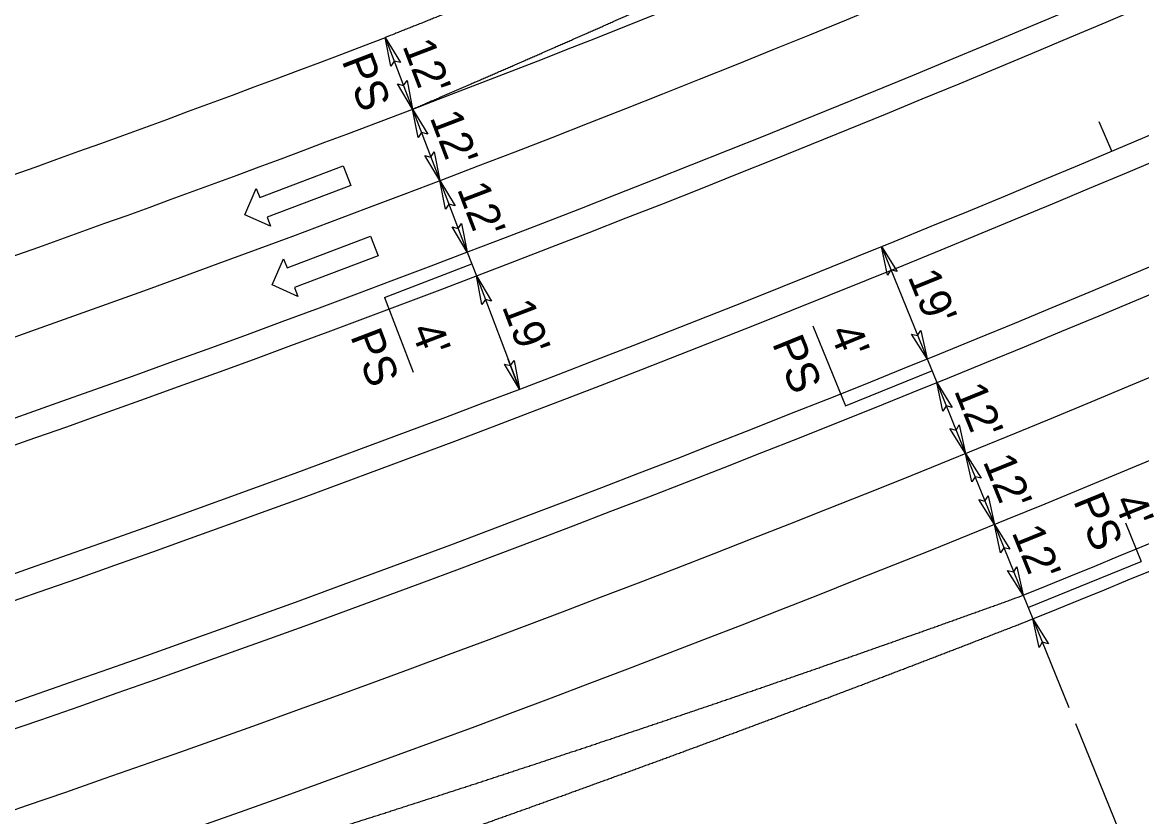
# Model space of a CAD drawing. Extents: x 2389694 to 2405615, y 546931 to 573532.
# Drawn here: x 2391294.1 to 2391469.5, y 552698.7 to 552823.2 of the extents above; entities that cross this region are included whole.
import ezdxf

# ---------------------------------------------------------------- set-up
doc = ezdxf.new("R2010")
doc.units = 0
for name, color, linetype in [('Prop Cable Guiderail Double Face', 7, 'Continuous'), ('Prop Dimension', 7, 'Continuous'), ('Prop Dimension Text', 7, 'Continuous'), ('Prop EOT', 7, 'Continuous'), ('Prop Horizontal Alignment', 7, 'Continuous'), ('Prop Horizontal Alignment Tick Small', 7, 'Continuous'), ('Prop Lane Arrow Through CELL', 7, 'Continuous'), ('Prop Lane Lines', 7, 'Continuous')]:
    doc.layers.add(name, color=color, linetype=linetype)

msp = doc.modelspace()

# ---------------------------------------------------------------- linework, layer by layer
at = {"layer": 'Prop Cable Guiderail Double Face'}
msp.add_arc((2390350.01, 555442.22), 2869, 286.11768, 302.22693, dxfattribs=at)
at = {"layer": 'Prop Dimension'}
for p, q in [((2391350.94, 552820.82), (2391355.22, 552809.61)), ((2391355.22, 552809.61), (2391359.5, 552798.4)), ((2391359.5, 552798.4), (2391363.78, 552787.19)), ((2391428.68, 552788.04), (2391435.84, 552770.44)), ((2391363.78, 552787.19), (2391365.21, 552783.45)), ((2391350.8, 552780.09), (2391364.5, 552785.32)), ((2391365.21, 552783.45), (2391371.99, 552765.7)), ((2391350.8, 552780.09), (2391355.28, 552768.37)), ((2391417.95, 552775.62), (2391423.04, 552763.08)), ((2391435.84, 552770.44), (2391437.34, 552766.73)), ((2391423.04, 552763.08), (2391436.59, 552768.59)), ((2391437.34, 552766.73), (2391441.86, 552755.62)), ((2391441.86, 552755.62), (2391446.38, 552744.5)), ((2391446.38, 552744.5), (2391450.9, 552733.38)), ((2391466.94, 552744.76), (2391469.4, 552738.69)), ((2391451.79, 552731.53), (2391469.4, 552738.69)), ((2391450.9, 552733.38), (2391452.41, 552729.68)), ((2391452.41, 552729.68), (2391458.05, 552715.78)), ((2391459.07, 552713.28), (2391468.06, 552691.16))]:
    msp.add_line(p, q, dxfattribs=at)
for points in [[(2391351.82, 552816.34), (2391350.94, 552820.82), (2391353.3, 552816.88), (2391352.35, 552817.13)], [(2391354.34, 552814.09), (2391355.22, 552809.61), (2391352.86, 552813.55), (2391353.81, 552813.3)], [(2391356.1, 552805.13), (2391355.22, 552809.61), (2391357.58, 552805.67), (2391356.63, 552805.92)], [(2391358.62, 552802.88), (2391359.5, 552798.4), (2391357.14, 552802.34), (2391358.09, 552802.09)], [(2391360.38, 552793.92), (2391359.5, 552798.4), (2391361.87, 552794.46), (2391360.91, 552794.71)], [(2391362.9, 552791.67), (2391363.78, 552787.19), (2391361.42, 552791.13), (2391362.38, 552790.88)], [(2391429.66, 552783.58), (2391428.68, 552788.04), (2391431.13, 552784.15), (2391430.17, 552784.38)], [(2391366.09, 552778.97), (2391365.21, 552783.45), (2391367.57, 552779.51), (2391366.62, 552779.76)], [(2391434.86, 552774.9), (2391435.84, 552770.44), (2391433.39, 552774.33), (2391434.35, 552774.1)], [(2391371.11, 552770.18), (2391371.99, 552765.7), (2391369.63, 552769.64), (2391370.58, 552769.39)], [(2391438.32, 552762.27), (2391437.34, 552766.73), (2391439.79, 552762.84), (2391438.83, 552763.07)], [(2391440.89, 552760.08), (2391441.86, 552755.62), (2391439.42, 552759.51), (2391440.38, 552759.28)], [(2391442.84, 552751.16), (2391441.86, 552755.62), (2391444.31, 552751.72), (2391443.35, 552751.96)], [(2391445.4, 552748.96), (2391446.38, 552744.5), (2391443.94, 552748.39), (2391444.89, 552748.16)], [(2391447.36, 552740.04), (2391446.38, 552744.5), (2391448.83, 552740.61), (2391447.87, 552740.84)], [(2391449.92, 552737.84), (2391450.9, 552733.38), (2391448.45, 552737.27), (2391449.41, 552737.04)], [(2391453.38, 552725.21), (2391452.41, 552729.68), (2391454.85, 552725.78), (2391453.89, 552726.02)]]:
    msp.add_lwpolyline(points, close=True, dxfattribs=at)
at = {"layer": 'Prop EOT'}
for radius, start, end in [(2842, 286.11768, 302.22693), (2846, 286.11763, 302.22693), (2884, 286.11768, 302.22693), (2888, 286.11768, 302.22693), (2924, 292.11719, 302.22692), (2928, 292.11719, 302.22692), (2806, 286.11768, 290.89848), (2818, 286.11768, 290.89849)]:
    msp.add_arc((2390350.01, 555442.22), radius, start, end, dxfattribs=at)
for points in [[(2391405.32, 552843.1), (2391404.59, 552842.79), (2391403.85, 552842.48), (2391403.12, 552842.17), (2391402.39, 552841.86), (2391401.66, 552841.56), (2391400.93, 552841.25), (2391400.19, 552840.94), (2391399.46, 552840.63), (2391398.73, 552840.32), (2391398, 552840.02), (2391397.26, 552839.71), (2391396.53, 552839.41), (2391395.8, 552839.1), (2391395.07, 552838.79), (2391394.34, 552838.49), (2391393.6, 552838.18), (2391392.87, 552837.88), (2391392.14, 552837.57), (2391391.4, 552837.27), (2391390.67, 552836.96), (2391389.93, 552836.66), (2391389.2, 552836.35), (2391388.47, 552836.05), (2391387.73, 552835.75), (2391387, 552835.44), (2391386.27, 552835.14), (2391385.54, 552834.84), (2391384.8, 552834.53), (2391384.07, 552834.23), (2391383.34, 552833.93), (2391382.59, 552833.62), (2391381.86, 552833.32), (2391381.13, 552833.02), (2391380.39, 552832.72), (2391379.66, 552832.42), (2391378.92, 552832.12), (2391378.19, 552831.82), (2391377.46, 552831.51), (2391376.72, 552831.21), (2391375.99, 552830.91), (2391375.25, 552830.61), (2391374.52, 552830.31), (2391373.78, 552830.01), (2391373.04, 552829.71), (2391372.31, 552829.41), (2391371.57, 552829.11), (2391370.84, 552828.81), (2391370.1, 552828.52), (2391369.37, 552828.22), (2391368.63, 552827.92), (2391367.9, 552827.62), (2391367.16, 552827.32), (2391366.42, 552827.03), (2391365.69, 552826.73), (2391364.95, 552826.43), (2391364.21, 552826.13), (2391363.47, 552825.83), (2391362.74, 552825.54), (2391362, 552825.24), (2391361.27, 552824.95), (2391360.53, 552824.65), (2391359.79, 552824.35), (2391359.06, 552824.06), (2391358.32, 552823.76), (2391357.58, 552823.47), (2391356.85, 552823.17), (2391356.11, 552822.88), (2391355.36, 552822.58), (2391354.63, 552822.29), (2391353.89, 552821.99), (2391353.15, 552821.7), (2391352.42, 552821.41), (2391350.94, 552820.82)], [(2391355.22, 552809.61), (2391355.96, 552809.92), (2391356.69, 552810.24), (2391357.42, 552810.55), (2391358.15, 552810.87), (2391358.89, 552811.18), (2391359.62, 552811.5), (2391360.36, 552811.82), (2391361.09, 552812.13), (2391361.82, 552812.45), (2391362.56, 552812.77), (2391363.29, 552813.08), (2391364.02, 552813.4), (2391364.75, 552813.72), (2391365.48, 552814.03), (2391366.21, 552814.35), (2391366.94, 552814.67), (2391367.67, 552814.99), (2391368.41, 552815.31), (2391369.15, 552815.63), (2391369.88, 552815.95), (2391370.61, 552816.26), (2391371.34, 552816.58), (2391372.07, 552816.9), (2391372.8, 552817.22), (2391373.53, 552817.54), (2391374.26, 552817.86), (2391374.99, 552818.18), (2391375.72, 552818.5), (2391376.45, 552818.82), (2391377.18, 552819.14), (2391377.92, 552819.47), (2391378.65, 552819.79), (2391379.38, 552820.11), (2391380.11, 552820.43), (2391380.84, 552820.75), (2391381.57, 552821.07), (2391382.29, 552821.39), (2391383.02, 552821.72), (2391383.75, 552822.04), (2391384.48, 552822.36), (2391385.21, 552822.68), (2391385.94, 552823.01), (2391386.67, 552823.33), (2391387.4, 552823.66), (2391388.13, 552823.98), (2391388.86, 552824.3), (2391389.59, 552824.63), (2391390.32, 552824.95), (2391391.05, 552825.28), (2391391.77, 552825.6), (2391392.5, 552825.93), (2391393.23, 552826.25), (2391393.96, 552826.58), (2391394.68, 552826.9), (2391395.41, 552827.23), (2391396.15, 552827.56), (2391396.87, 552827.88), (2391397.6, 552828.21), (2391398.33, 552828.54), (2391399.06, 552828.86), (2391399.78, 552829.19), (2391400.51, 552829.52), (2391401.23, 552829.84), (2391401.96, 552830.17), (2391402.69, 552830.5), (2391403.41, 552830.83), (2391404.14, 552831.15), (2391404.88, 552831.49), (2391405.6, 552831.81), (2391406.33, 552832.14), (2391407.05, 552832.47), (2391407.78, 552832.8), (2391408.5, 552833.13), (2391409.23, 552833.46)], [(2391393.07, 552713.17), (2391393.86, 552713.43), (2391394.64, 552713.7), (2391395.42, 552713.96), (2391396.21, 552714.23), (2391396.99, 552714.49), (2391397.77, 552714.76), (2391398.56, 552715.03), (2391399.35, 552715.29), (2391400.13, 552715.56), (2391400.91, 552715.83), (2391401.69, 552716.09), (2391402.48, 552716.36), (2391403.26, 552716.63), (2391404.04, 552716.9), (2391404.82, 552717.16), (2391405.61, 552717.43), (2391406.39, 552717.7), (2391407.17, 552717.97), (2391407.96, 552718.24), (2391408.74, 552718.51), (2391409.52, 552718.78), (2391410.31, 552719.05), (2391411.09, 552719.32), (2391411.87, 552719.59), (2391412.65, 552719.86), (2391413.43, 552720.13), (2391414.21, 552720.4), (2391415, 552720.67), (2391415.78, 552720.94), (2391416.56, 552721.21), (2391417.35, 552721.49), (2391418.13, 552721.76), (2391418.91, 552722.03), (2391419.69, 552722.3), (2391420.47, 552722.58), (2391421.25, 552722.85), (2391422.03, 552723.12), (2391422.81, 552723.39), (2391423.59, 552723.67), (2391424.37, 552723.94), (2391425.16, 552724.21), (2391425.94, 552724.49), (2391426.72, 552724.76), (2391427.51, 552725.04), (2391428.29, 552725.32), (2391429.07, 552725.59), (2391429.85, 552725.86), (2391430.63, 552726.14), (2391431.41, 552726.42), (2391432.19, 552726.69), (2391432.96, 552726.97), (2391433.74, 552727.24), (2391434.52, 552727.52), (2391435.3, 552727.8), (2391436.08, 552728.07), (2391436.87, 552728.35), (2391437.65, 552728.63), (2391438.43, 552728.91), (2391439.21, 552729.19), (2391439.99, 552729.46), (2391440.77, 552729.74), (2391441.55, 552730.02), (2391442.33, 552730.3), (2391443.1, 552730.58), (2391443.88, 552730.86), (2391444.66, 552731.14), (2391445.44, 552731.42), (2391446.23, 552731.7), (2391447.01, 552731.98), (2391447.79, 552732.26), (2391448.56, 552732.54), (2391449.34, 552732.82), (2391450.9, 552733.38)], [(2391395.07, 552707.93), (2391395.85, 552708.22), (2391396.63, 552708.51), (2391397.4, 552708.79), (2391398.18, 552709.08), (2391398.96, 552709.36), (2391399.73, 552709.65), (2391400.52, 552709.94), (2391401.3, 552710.23), (2391402.07, 552710.52), (2391402.85, 552710.8), (2391403.62, 552711.09), (2391404.4, 552711.38), (2391405.18, 552711.67), (2391405.95, 552711.95), (2391406.73, 552712.24), (2391407.5, 552712.53), (2391408.28, 552712.82), (2391409.05, 552713.11), (2391409.84, 552713.4), (2391410.62, 552713.69), (2391411.39, 552713.98), (2391412.17, 552714.27), (2391412.94, 552714.56), (2391413.72, 552714.85), (2391414.49, 552715.15), (2391415.27, 552715.44), (2391416.04, 552715.73), (2391416.82, 552716.02), (2391417.59, 552716.31), (2391418.36, 552716.6), (2391419.15, 552716.9), (2391419.92, 552717.19), (2391420.7, 552717.48), (2391421.47, 552717.78), (2391422.25, 552718.07), (2391423.02, 552718.36), (2391423.79, 552718.66), (2391424.57, 552718.95), (2391425.34, 552719.24), (2391426.12, 552719.54), (2391426.89, 552719.83), (2391427.66, 552720.13), (2391428.44, 552720.42), (2391429.22, 552720.72), (2391429.99, 552721.01), (2391430.77, 552721.31), (2391431.54, 552721.61), (2391432.31, 552721.9), (2391433.09, 552722.2), (2391433.86, 552722.49), (2391434.63, 552722.79), (2391435.4, 552723.09), (2391436.18, 552723.38), (2391436.95, 552723.68), (2391437.72, 552723.98), (2391438.5, 552724.28), (2391439.28, 552724.58), (2391440.05, 552724.88), (2391440.82, 552725.17), (2391441.59, 552725.47), (2391442.37, 552725.77), (2391443.14, 552726.07), (2391443.91, 552726.37), (2391444.68, 552726.67), (2391445.45, 552726.97), (2391446.22, 552727.27), (2391447, 552727.57), (2391447.78, 552727.87), (2391448.55, 552728.17), (2391449.32, 552728.47), (2391450.09, 552728.77), (2391450.86, 552729.07), (2391452.4, 552729.68)], [(2391334.89, 552694.18), (2391335.67, 552694.43), (2391336.46, 552694.68), (2391337.25, 552694.93), (2391338.04, 552695.17), (2391338.83, 552695.42), (2391339.61, 552695.67), (2391340.41, 552695.93), (2391341.2, 552696.17), (2391341.98, 552696.42), (2391342.77, 552696.67), (2391343.56, 552696.92), (2391344.35, 552697.18), (2391345.13, 552697.43), (2391345.92, 552697.68), (2391346.71, 552697.93), (2391347.49, 552698.18), (2391348.28, 552698.43), (2391349.07, 552698.68), (2391349.86, 552698.94), (2391350.65, 552699.19), (2391351.44, 552699.44), (2391352.22, 552699.7), (2391353.01, 552699.95), (2391353.8, 552700.2), (2391354.58, 552700.46), (2391355.37, 552700.71), (2391356.16, 552700.96), (2391356.94, 552701.22), (2391357.73, 552701.47), (2391358.51, 552701.73), (2391359.31, 552701.98), (2391360.1, 552702.24), (2391360.88, 552702.5), (2391361.67, 552702.75), (2391362.45, 552703.01), (2391363.24, 552703.26), (2391364.02, 552703.52), (2391364.81, 552703.78), (2391365.6, 552704.03), (2391366.38, 552704.29), (2391367.17, 552704.55), (2391367.95, 552704.8), (2391368.74, 552705.06), (2391369.53, 552705.32), (2391370.32, 552705.58), (2391371.1, 552705.84), (2391371.89, 552706.1), (2391372.67, 552706.35), (2391373.46, 552706.61), (2391374.24, 552706.87), (2391375.03, 552707.13), (2391375.81, 552707.39), (2391376.59, 552707.65), (2391377.38, 552707.91), (2391378.16, 552708.17), (2391378.96, 552708.44), (2391379.74, 552708.7), (2391380.53, 552708.96), (2391381.31, 552709.22), (2391382.09, 552709.48), (2391382.88, 552709.74), (2391383.66, 552710), (2391384.45, 552710.27), (2391385.23, 552710.53), (2391386.01, 552710.79), (2391386.8, 552711.05), (2391387.58, 552711.32), (2391388.37, 552711.58), (2391389.16, 552711.85), (2391389.94, 552712.11), (2391390.72, 552712.37), (2391391.51, 552712.64), (2391392.29, 552712.9), (2391393.07, 552713.17)], [(2391337.32, 552687.4), (2391338.1, 552687.67), (2391338.88, 552687.94), (2391339.66, 552688.21), (2391340.45, 552688.48), (2391341.23, 552688.75), (2391342.01, 552689.02), (2391342.8, 552689.29), (2391343.58, 552689.57), (2391344.37, 552689.84), (2391345.15, 552690.11), (2391345.93, 552690.38), (2391346.71, 552690.65), (2391347.49, 552690.92), (2391348.27, 552691.19), (2391349.06, 552691.47), (2391349.84, 552691.74), (2391350.62, 552692.01), (2391351.4, 552692.28), (2391352.19, 552692.56), (2391352.97, 552692.83), (2391353.75, 552693.11), (2391354.53, 552693.38), (2391355.31, 552693.65), (2391356.09, 552693.93), (2391356.87, 552694.2), (2391357.66, 552694.48), (2391358.44, 552694.75), (2391359.22, 552695.03), (2391360, 552695.3), (2391360.78, 552695.58), (2391361.57, 552695.86), (2391362.35, 552696.13), (2391363.13, 552696.41), (2391363.91, 552696.69), (2391364.69, 552696.96), (2391365.47, 552697.24), (2391366.25, 552697.52), (2391367.03, 552697.79), (2391367.81, 552698.07), (2391368.59, 552698.35), (2391369.37, 552698.63), (2391370.14, 552698.91), (2391370.92, 552699.18), (2391371.71, 552699.47), (2391372.49, 552699.74), (2391373.27, 552700.02), (2391374.05, 552700.3), (2391374.83, 552700.58), (2391375.61, 552700.86), (2391376.39, 552701.14), (2391377.17, 552701.42), (2391377.94, 552701.7), (2391378.72, 552701.98), (2391379.5, 552702.26), (2391380.28, 552702.55), (2391381.07, 552702.83), (2391381.85, 552703.11), (2391382.62, 552703.39), (2391383.4, 552703.68), (2391384.18, 552703.96), (2391384.96, 552704.24), (2391385.74, 552704.52), (2391386.51, 552704.81), (2391387.29, 552705.09), (2391388.07, 552705.37), (2391388.85, 552705.66), (2391389.62, 552705.94), (2391390.41, 552706.23), (2391391.19, 552706.51), (2391391.97, 552706.8), (2391392.74, 552707.08), (2391393.52, 552707.36), (2391394.3, 552707.65), (2391395.07, 552707.93)]]:
    msp.add_spline(points, degree=3, dxfattribs=at)
at = {"layer": 'Prop Horizontal Alignment'}
msp.add_arc((2390350.01, 555442.22), 2865, 286.11768, 302.22693, dxfattribs=at)
at = {"layer": 'Prop Horizontal Alignment Tick Small'}
for p, q in [((2391464.77, 552802.99), (2391462.82, 552807.6)), ((2391371.99, 552765.7), (2391370.21, 552770.37))]:
    msp.add_line(p, q, dxfattribs=at)
at = {"layer": 'Prop Lane Arrow Through CELL'}
for p, q in [((2391331.26, 552795.75), (2391344.35, 552800.71)), ((2391344.35, 552800.71), (2391345.52, 552797.62)), ((2391328.91, 552793.04), (2391330.72, 552797.15)), ((2391330.72, 552797.15), (2391331.26, 552795.75)), ((2391345.52, 552797.62), (2391332.42, 552792.66)), ((2391332.96, 552791.26), (2391328.91, 552793.04)), ((2391332.42, 552792.66), (2391332.96, 552791.26)), ((2391335.54, 552784.73), (2391348.63, 552789.69)), ((2391348.63, 552789.69), (2391349.8, 552786.61)), ((2391333.2, 552782.03), (2391335.01, 552786.14)), ((2391335.01, 552786.14), (2391335.54, 552784.73)), ((2391349.8, 552786.61), (2391336.71, 552781.65)), ((2391337.24, 552780.24), (2391333.2, 552782.03)), ((2391336.71, 552781.65), (2391337.24, 552780.24))]:
    msp.add_line(p, q, dxfattribs=at)
at = {"layer": 'Prop Lane Lines'}
for radius, start, end in [(2818, 290.89849, 302.22692), (2830, 286.11768, 302.22693), (2900, 286.11768, 302.22693), (2912, 286.11768, 302.22693)]:
    msp.add_arc((2390350.01, 555442.22), radius, start, end, dxfattribs=at)

# ---------------------------------------------------------------- texts
at = {"layer": 'Prop Dimension Text'}
for s, rotation, p in [("12'", 290.8991, (2391353.58, 552819.52)), ('PS', 290.8981, (2391344.06, 552817.2)), ("12'", 290.8974, (2391357.86, 552808.3)), ("12'", 290.8991, (2391362.14, 552797.09)), ("19'", 292.1176, (2391432.76, 552783.33)), ("19'", 290.8984, (2391369.18, 552778.65)), ('PS', 290.8981, (2391345.4, 552774.01)), ("4'", 290.8981, (2391354.88, 552775.03)), ('PS', 292.1167, (2391411.5, 552772.89)), ("4'", 292.1167, (2391420.49, 552774.68)), ("12'", 292.1177, (2391440.01, 552765.48)), ("12'", 292.118, (2391444.53, 552754.37)), ('PS', 292.1169, (2391458.69, 552748.21)), ("4'", 292.1169, (2391465.02, 552748.13)), ("12'", 292.1167, (2391449.05, 552743.25))]:
    msp.add_text(s, height=5, rotation=rotation, dxfattribs=at).set_placement(p)

doc.saveas('drawing.dxf')
